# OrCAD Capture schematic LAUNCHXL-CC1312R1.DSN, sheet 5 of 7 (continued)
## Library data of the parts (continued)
U15 = IC_PROC_USB3300_QFN32: IC, DIGITAL, INTERFACE, HI-SPEED USB HOST, 3.3V, QFN32-EP, SMD; ALT_SYMBOLS: QFNWB50P500X500X100-33L,QFNWB50P500X500X100-33M,QFNWB50P500X500X100-33DL,QFNWB50P500X500X100-33DM; AutoDoc File: https://notefied-dynamic-precision.com/DB/Apps/Desktop/Item/Object.aspx?id=73764; BU Name: DYNAMIC PRECISION GDANSK; Budget Currency: USD; Budget Price: 0.91; Client Status: UNDER_REVIEW; Country of Origin: CHINA; Datasheet URL 1: http://ww1.microchip.com/downloads/en/DeviceDoc/00001783B.pdf; Datasheet URL 2: http://www.microchip.com/wwwproducts/Devices.aspx?product=USB3300#pricindAndSamples; FPLIST: QFNWB50P500X500X100-33N,QFNWB50P500X500X100-33DN; Last Time Buy: N/A; Lead Time: 2; Max Oper Temp: +85DEGC; Min Oper Temp: -40DEGC; Mounting Type: SMD; PCB Package: QFN32-EP; Packing Size: 4900; Packing Type: TRAY; Part Number: 18-26311; Part Type: IC\DIGITAL\INTERFACE\USB; Revision: R002; RoHS Status: ROHS_COMPLIANT; Rtd Voltage: 3.3V; Vendor: MICROCHIP; Vendor Part Status: ACTIVE; Weight: 0.0636g
Y3 = XTAL_4: CRYSTAL, OSCILLATOR, 16MHz, -30PPM/DEGC/+30PPM/DEGC, -40DEGC/+85DEGC, SMD; ALT_SYMBOLS: OSCCC250X320X100-4BL,OSCCC250X320X100-4BM; AutoDoc File: http://notefied-dynamic-precision.com/DB/Apps/Desktop/Item/Object.aspx?id=96470; Datasheet URL 1: N/A; Datasheet URL 2: http://www.ndk.com/images/products/catalog/c_NX3225GA-STD-CRG-2_e.pdf; FPLIST: OSCCC250X320X100-4BN,OSCCC250X320X100-4BL,OSCCC250X320X100-4BM; MPN: NX3225GA-16.000M-STD-CRG-1; MPN Status: ACTIVE; Manufacturer: NIHON DEMPA KOGYO; Max Oper Temp: +85DEGC; Max TC: +30PPM/DEGC; Max Tol: +20PPM; Min Oper Temp: -40DEGC; Min TC: -30PPM/DEGC; Min Tol: -20PPM; Mounting Type: SMD; NOTE Status: PREFERRED; Part Number: 12-00745; Part Type: CRYSTAL\OSCILLATOR; Revision: R001; RoHS Status: ROHS_COMPLIANT
Y4 = XTAL_4: CRYSTAL, RESONATOR, 24MHz, -50PPM/+50PPM, -40DEGC/+85DEGC, SMD; ALT_SYMBOLS: OSCCC250X320X70-4AL,OSCCC250X320X70-4AM; AutoDoc File: https://notefied-dynamic-precision.com/DB/Apps/Desktop/Item/Object.aspx?id=96049; BU Name: DYNAMIC PRECISION GDANSK; Budget Currency: N/A; Budget Price: N/A; Capacitance: 12pF; Client Status: UNDER_REVIEW; Country of Origin: JAPAN; Datasheet URL 1: https://support.epson.biz/td/api/doc_check.php?mode=dl&lang=en&Parts=FA-238; Datasheet URL 2: http://www5.epsondevice.com/en/products/mhz_range/fa238.html; Last Time Buy: N/A; Lead Time: N/A; Max Oper Temp: +85DEGC; Max TC: +50PPM; Max Tol: +50PPM; Min Oper Temp: -40DEGC; Min TC: -50PPM; Min Tol: -50PPM; Mounting Type: SMD; Packing Size: 1000; Packing Type: TAPE_&_REEL; Part Number: 12-00730; Part Type: CRYSTAL\RESONATOR; Revision: R002; RoHS Status: ROHS_COMPLIANT; Rtd Voltage: N/A; Vendor: EPSON; Vendor Part Number: FA-238 24.0000MB50X-W0; Vendor Part Status: ACTIVE; Weight: 0.016g

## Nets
5V0: C48.1 C149.2 C150.1 FL2.1 TP10.1 U7.1(IN) U7.2(IN) U7.8(EN) ; also on sheet 1 4
GND: C1.2 C2.2 C3.2 C4.2 C6.2 C7.2 C8.2 C9.2 C38.2 C39.2 C40.2 C42.2 C43.2 C44.2 C45.2 C46.2 C48.2 C49.2 C50.2 C77.2 C78.2 C79.2 C80.2 C83.2 C84.2 C85.1 C86.1 C87.2 C88.1 C89.1 C149.1 C150.2 C151.2 CR4.1(C) CR5.1(C) CR6.3 J6.5(GND) P8.3(7) P8.5(8) P8.9(10) R21.2 R28.1 R29.2 R30.2 R32.1 R34.1 R84.1 R85.1 R113.1 R114.1 R116.2 U5.10(GNDA) U5.17(GND) U5.48(GND) U5.55(GND) U5.58(GND) U5.64(nWAKE) U5.66(XOSC0) U5.80(GND) U5.114(GND) U6.1(ANODE) U7.6(GND) U7.9(GND/TAB) U15.1(GND) U15.2(GND) U15.33(EGP) Y3.2 Y3.4 Y4.2 Y4.4 ; also on sheet 1 2 3 4 6 7
VBUS_DET: R115.1 R116.1 U5.12(PE3/AIN0)
VDDC: C43.1 C44.1 C45.1 U5.87(VDDC) U5.115(VDDC)
ET_CAL0: U5.74(PM4) ; also on sheet 2
ET_CAL1: U5.73(PM5) ; also on sheet 2
ET_CAL2: U5.23(PC6/C0+) ; also on sheet 2
ET_CALIBRATE: U5.77(PM1) ; also on sheet 4
ET_PM2: U5.76(PM2) ; also on sheet 2
ET_PN3: U5.110(PN3) ; also on sheet 2
ET_SSICLK: U5.120(PB5/AIN11) ; also on sheet 2
ET_SSIDAT0: U5.123(PE4/AIN9) ; also on sheet 2
ET_SSIDAT1: U5.124(PE5/AIN8) ; also on sheet 2
ET_SSIFSS: U5.121(PB4/AIN10) ; also on sheet 2
IRSTn: P8.10(5) R20.2
ITCK: P8.4(2) U5.100(PC0/TCK/SWCLK)
ITDI: P8.8(4) U5.98(PC2/TDI)
ITDO: P8.6(3) U5.97(PC3/TDO/SWO)
ITMS: P8.2(1) U5.99(PC1/TMS/SWDIO)
SENSE_R_BYPASS: U5.78(PM0) ; also on sheet 4
USB1V8: C83.1 C84.1 C85.2 U15.15(VDD1.8) U15.26(VDD1.8)
USB_VBUS: C77.1 C82.1 CR6.6 J6.1(VCC) Q1.2(S) R82.2 R86.2 R115.2
USBCLK: U5.92(PB3/I2C0SDA) U15.14(CLKOUT)
USBD0: U5.81(PL0) U15.24(DATA0)
USBD1: U5.82(PL1) U15.23(DATA1)
USBD2: U5.83(PL2) U15.22(DATA2)
USBD3: U5.84(PL3) U15.21(DATA3)
USBD4: U5.85(PL4) U15.20(DATA4)
USBD5: U5.86(PL5) U15.19(DATA5)
USBD6: U5.106(PP5) U15.18(DATA6)
USBD7: U5.105(PP4) U15.17(DATA7)
USBDIR: U5.104(PP3) U15.12(DIR)
USBDM: CR6.5 J6.2(D-) U15.8(DM)
USBDP: CR6.4 J6.3(D+) U15.7(DP)
USBID: CR6.2 J6.4(ID)
USBNXT: U5.103(PP2) U15.11(NXT)
USBSTP: U5.91(PB2/I2C0SCL) U15.13(STP)
XDS_RESET: U5.40(PA6) ; also on sheet 4
XDS_RX: U5.33(PA0/U0RX) ; also on sheet 4
XDS_SWO: U5.25(PC4/C1-) ; also on sheet 4
XDS_TCK: U5.35(PA2/SSI0CLK) ; also on sheet 4
XDS_TDI: U5.38(PA5/SSI0XDAT1) ; also on sheet 4
XDS_TDO: U5.37(PA4/SSI0XDAT0) ; also on sheet 4
XDS_TMS: U5.36(PA3/SSI0FSS) ; also on sheet 4
XDS_TMS_DIR: U5.24(PC5/C1+) ; also on sheet 4
XDS_TX: U5.34(PA1/U0TX) ; also on sheet 4
XDS_VCC: C2.1 C3.1 C4.1 C6.1 C7.1 C38.1 C39.1 C40.1 C42.1 C47.1 C49.1 C78.1 C79.1 C80.1 P8.1(6) R17.2 R18.2 R27.1 R31.2 R33.2 R39.1 R83.1 TP11.1 U5.7(VDD) U5.8(VDDA) U5.16(VDD) U5.26(VDD) U5.28(VDD) U5.39(VDD) U5.47(VDD) U5.51(VDD) U5.52(VDD) U5.69(VDD) U5.79(VDD) U5.90(VDD) U5.101(VDD) U5.113(VDD) U5.122(VDD) U7.3(OUT) U7.4(OUT) U15.6(VDD3.3) U15.16(VDD3.3) U15.25(VDD3.3) U15.30(VDD3.3) U15.31(REG_EN) ; also on sheet 4
N949215: R17.1 R20.1 R21.1 U5.70(nRST)
N949243: R30.1 U5.60(PK7)
N949263: C47.2 R33.1 R34.2 U7.5(FB)
N949375: R28.2 U5.59(RBIAS)
N949687: C1.1 U5.89(OSC1) Y3.3
N949695: C9.1 U5.88(OSC0) Y3.1
N950083: C8.1 C50.1 R18.1 U5.9(VREFA+) U6.3(CATHODE)
N951001: R39.2 U5.63(PK4)
N951013: R29.1 U5.61(PK6)
N951017: R27.2 U5.62(PK5)
N952443: C46.1 R31.1 U5.68(VBAT)
N1004371: R23.2 U5.3(PD2/AIN13)
N1004534: R25.2 U5.4(PD3/AIN12)
N1031635: CR6.1 J6.M1(SHIELD1) J6.M2(SHIELD2) R32.2
N1548408: R82.1 U15.4(VBUS)
N1553941: R83.2 U15.5(ID)
N1559020: C82.2 Q1.1(G) R85.2
N1559161: C151.1 FL2.2 Q1.3(D) R86.1
N1567630: C86.2 C87.1 U15.29(VDDA1.8)
N1579665: R84.2 U15.32(RBIAS)
N1580179: C88.2 R87.2 U15.28(XI) Y4.1
N1580186: C89.2 R87.1 U15.27(XO) Y4.3
N1644260: R114.2 U5.95(PB0/USB0ID)
N1644363: R113.2 U5.96(PB1/USB0VBUS)
N2366159: CR4.2(A) R23.1
N2366162: CR5.2(A) R25.1

Not connected (* = marked no-connect by the designer): P8 7(9)*; U5 1(PD0/AIN15)* 2(PD1/AIN14)* 5(PQ0)* 6(PQ1)* 11(PQ2)* 13(PE2/AIN1)* 14(PE1/AIN2)* 15(PE0/AIN3)* 18(PK0/AIN16)* 19(PK1/AIN17)* 20(PK2/AIN18)* 21(PK3/AIN19)* 22(PC7/C0-)* 27(PQ3)* 29(PH0) 30(PH1) 31(PH2)* 32(PH3)* 41(PA7) 42(PF0)* 43(PF1)* 44(PF2)* 45(PF3)* 46(PF4)* 49(PG0)* 50(PG1)* 53(EN0RXIN)* 54(EN0RXIP)* 56(EN0TXON)* 57(EN0TXOP)* 65(nHIB)* 67(XOSC1)* 71(PM7)* 72(PM6)* 75(PM3)* 93(PL7/USB0DM)* 94(PL6/USB0DP)* 102(PQ4)* 107(PN0)* 108(PN1)* 109(PN2)* 111(PN4)* 112(PN5)* 116(PJ0)* 117(PJ1)* 118(PP0/C2+)* 119(PP1/C2-)* 125(PD4/AIN7)* 126(PD5/AIN6)* 127(PD6/AIN5)* 128(PD7/AIN4)*; U6 2(NC)* 4(NC)* 5(NC)*; U7 7(NC)*; U15 3(CPEN)* 9(RESET)* 10(EXTVBUS)*

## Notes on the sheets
sheet 5
- XDS110 Debugger
- Pin 28
- Pin 113
- Pin 101
- Pin 69
- Pin 51
- Inrush current limit
- XDS_VCC = 3.3 V
- WCS042B
